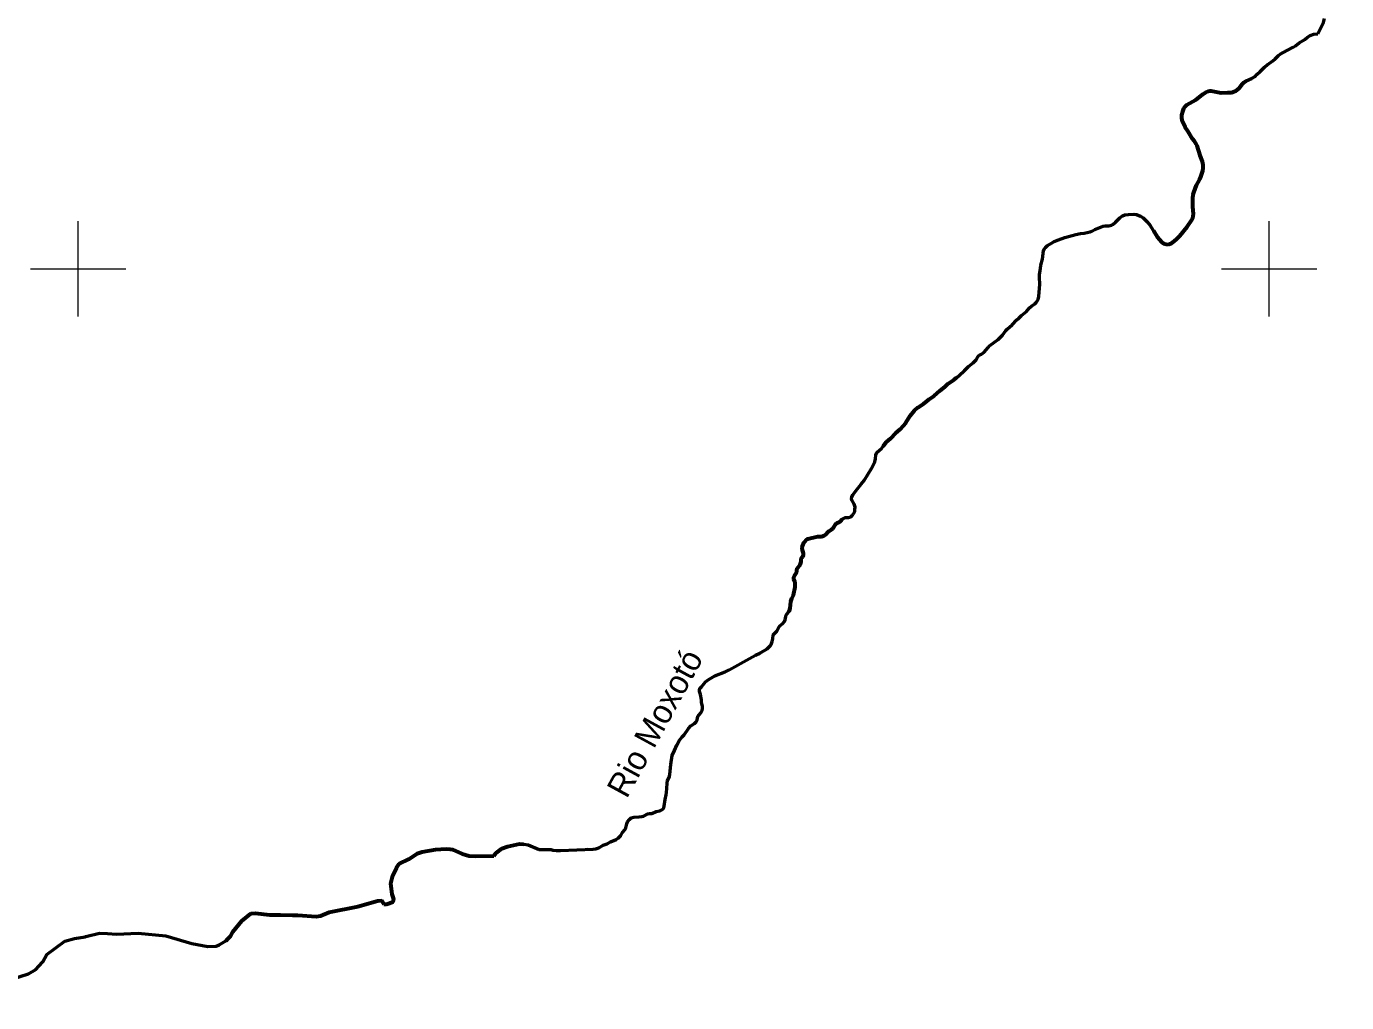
# Model space of a CAD drawing. Extents: x -1643653 to 4543381, y 1624270 to 13878484.
# Drawn here: x 598915 to 626625, y 8984602 to 9005087 of the extents above; entities that cross this region are included whole.
import ezdxf
from ezdxf.enums import TextEntityAlignment as Align

# ---------------------------------------------------------------- set-up
doc = ezdxf.new("R2010")
doc.units = 0
doc.header["$LTSCALE"] = 200
doc.linetypes.add('LONG_DASH_SHORT_DASH', pattern=[9.9, 6, -1.2, 1.5, -1.2])
for name, color, linetype, lineweight in [('1', 7, 'Continuous', 13), ('2', 7, 'Continuous', 13), ('24', 7, 'Continuous', 25), ('7', 7, 'LONG_DASH_SHORT_DASH', 60)]:
    doc.layers.add(name, color=color, linetype=linetype, lineweight=lineweight)
doc.layers.add('49', color=7, linetype='Continuous')

msp = doc.modelspace()

# ---------------------------------------------------------------- linework, layer by layer
at = {"layer": '1', "lineweight": 25}
msp.add_spline([(814781, 9009175.5), (814787.2, 9009173.4), (814796.9, 9009173.4), (814799.4, 9009172.4), (814805.1, 9009174.5), (814805.6, 9009176.5), (814811.7, 9009179.5), (814811.7, 9009179.5), (814801.5, 9009181), (814790.7, 9009181.5), (814784.1, 9009183.1), (814777.4, 9009185.1), (814778.4, 9009175.5)], degree=3, dxfattribs=at)
at = {"layer": '2'}
for p, q in [((600000, 8999000), (600000, 9001000)), ((625000, 8999000), (625000, 9001000)), ((599000, 9000000), (601000, 9000000)), ((624000, 9000000), (626000, 9000000))]:
    msp.add_line(p, q, dxfattribs=at)
at = {"layer": '24', "lineweight": 53}
for points in [[(626020.3, 9004931.6), (626138.4, 9005165.4), (626161, 9005249.2)], [(624968.7, 9004287.4), (625077.4, 9004367.4), (625125.3, 9004407.4), (625196.1, 9004475.4), (625232, 9004503.4), (625369.3, 9004583.4), (625507, 9004648.4), (625552.2, 9004680.4), (625627.3, 9004743.4), (625747.5, 9004813.4), (625804.8, 9004859.3), (625863.6, 9004898.3), (625936.5, 9004925.7), (626020.3, 9004931.6)], [(622356.1, 9001071.6), (622438.9, 9000988.6), (622501.2, 9000910.6), (622651.6, 9000673.6), (622694.8, 9000613.6), (622741.9, 9000562.6), (622781.6, 9000528.6), (622838, 9000513.6), (622887.5, 9000510.6), (622903.5, 9000513.6), (622951.5, 9000538.6), (623008.3, 9000580.6), (623061.1, 9000626.5), (623124.5, 9000694.5), (623279.2, 9000880.5), (623385, 9001031.5), (623398.2, 9001059.5), (623411.2, 9001147.5), (623406.1, 9001224.5), (623394.5, 9001300.5), (623396.9, 9001485.5), (623407.8, 9001557.5), (623420.7, 9001604.5), (623474.8, 9001753.5), (623546.5, 9001882.5), (623566.5, 9001928.5), (623606.4, 9002057.5), (623614.4, 9002114.5), (623615.2, 9002180.5), (623603.6, 9002252.5), (623548.9, 9002380.5), (623488.7, 9002579.5), (623465.3, 9002623.5), (623431.2, 9002675.5), (623387.3, 9002730.5), (623302, 9002882.5), (623235.1, 9002973.5), (623183.3, 9003094.5), (623167.7, 9003160.5), (623170, 9003229.5), (623186.6, 9003301.5), (623210, 9003362.5), (623241.9, 9003412.5), (623274.8, 9003442.5), (623462.1, 9003547.5), (623608.8, 9003667.5), (623666.2, 9003700.5), (623727.2, 9003726.5), (623755.6, 9003733.5), (623782.5, 9003731.5), (623993.5, 9003691.5), (624127.2, 9003701.5), (624209, 9003698.5), (624301.4, 9003736.4), (624324.7, 9003751.4), (624377.4, 9003798.4), (624433, 9003873.4), (624469.5, 9003912.4), (624514.8, 9003941.4), (624628.9, 9003992.4), (624709.5, 9004038.4), (624743.9, 9004077.4), (624810.6, 9004137.4), (624900.3, 9004230.4), (624968, 9004288.4)], [(620148.3, 8999353.7), (620168.6, 8999417.7), (620186.8, 8999678.7), (620178.1, 8999819.7), (620178.5, 8999880.7), (620194.3, 8999957.7), (620208.2, 9000078.7), (620242.8, 9000202.7), (620252.9, 9000329.7), (620263.2, 9000378.7), (620280.1, 9000412.7), (620305.3, 9000447.7), (620344.5, 9000485.7), (620432.6, 9000539.7), (620488.9, 9000569.7), (620581.6, 9000610.7), (620710.5, 9000657.7), (620939.4, 9000718.7), (621042.2, 9000740.6), (621118.4, 9000748.6), (621242.2, 9000776.6), (621275.5, 9000790.6), (621342.1, 9000826.6), (621518.2, 9000894.6), (621561.1, 9000901.6), (621637.2, 9000903.6), (621689.6, 9000916.6), (621716.6, 9000931.6), (621774.6, 9000977.6), (621867.2, 9001066.6), (621924.7, 9001110.6), (621967.5, 9001129.6), (622048.6, 9001140.6), (622160.3, 9001143.6), (622215.2, 9001136.6), (622300.1, 9001105.6), (622356.1, 9001071.6)], [(616275, 8994855), (616299.8, 8994916), (616306.6, 8994947), (616309.5, 8994997), (616289.9, 8995061), (616239.9, 8995143), (616235.6, 8995179), (616237.4, 8995206), (616262.8, 8995260), (616352.4, 8995378.9), (616439.6, 8995482.9), (616497.8, 8995558.9), (616654.6, 8995808.9), (616704.2, 8995904.9), (616721.4, 8995949.9), (616734.9, 8996009.9), (616742.4, 8996094.9), (616755.2, 8996130.9), (616770.5, 8996150.9), (616865.5, 8996231.9), (616968.5, 8996369.9), (617050.4, 8996439.9), (617160.7, 8996559.9), (617252.1, 8996633.9), (617320.9, 8996701.9), (617376, 8996767.9), (617466.2, 8996912.9), (617553.7, 8997026.9), (617627.5, 8997088.9), (617747.7, 8997167.8), (617821.7, 8997231.8), (617864.4, 8997264.8), (617970.3, 8997332.8), (618086, 8997441.8), (618201.6, 8997530.8), (618257.2, 8997582.8), (618380.8, 8997669.8), (618495.1, 8997763.8), (618608.2, 8997867.8), (618687.2, 8997947.8), (618784.2, 8998026.8), (618847.8, 8998091.8), (618880.8, 8998148.8), (618904.8, 8998177.8), (618927, 8998194.8), (618960.5, 8998211.8), (619017, 8998253.8), (619099.7, 8998350.8), (619132.8, 8998382.8), (619235.9, 8998457.8), (619310.3, 8998518.8), (619402.8, 8998610.8), (619472.9, 8998704.8), (619501.7, 8998736.7), (619608.1, 8998826.7), (619700.3, 8998928.7), (619746.9, 8998966.7), (619804.3, 8999021.7), (619907.6, 8999106.7), (619970.1, 8999177.7), (620010.3, 8999215.7), (620083.8, 8999267.7), (620109.1, 8999292.7), (620148.3, 8999353.7), (620148.3, 8999353.7)], [(615088.6, 8993660), (615092.1, 8993720), (615153, 8993790), (615174.6, 8993852), (615175.1, 8993904), (615179, 8993921), (615187.3, 8993934), (615211.5, 8993958), (615228.8, 8993992), (615227.7, 8994030), (615203.4, 8994096), (615199.3, 8994145), (615206.1, 8994178), (615239.1, 8994264), (615295.5, 8994325), (615320, 8994336), (615520.9, 8994382), (615601.5, 8994383), (615661.9, 8994403), (615699.6, 8994431), (615734.4, 8994474), (615755.4, 8994494), (615812.3, 8994527), (615840.8, 8994550), (615864.4, 8994578), (615900.1, 8994637), (615919.4, 8994659), (615934.8, 8994670), (615988.9, 8994692), (616008.8, 8994710), (616037.3, 8994745), (616076.4, 8994766), (616108.6, 8994778), (616169.1, 8994784), (616218.9, 8994795), (616250.2, 8994821), (616275, 8994855)], [(612374.7, 8989257.2), (612410.1, 8989349.2), (612422.8, 8989393.2), (612443.9, 8989595.2), (612472.1, 8989790.2), (612521.4, 8989889.2), (612567.7, 8990001.2), (612623.5, 8990108.2), (612679.4, 8990175.2), (612720.8, 8990217.2), (612815.3, 8990351.2), (612864.4, 8990407.2), (612937.9, 8990460.2), (612974.6, 8990496.2), (612997.1, 8990536.2), (613004.6, 8990605.2), (613071.9, 8990685.2), (613099.4, 8990741.2), (613104.8, 8990769.2), (613104.8, 8990813.2), (613086.3, 8990905.2), (613085.9, 8990954.2), (613066.1, 8991064.2), (613044.7, 8991133.2), (613043.4, 8991164.2), (613047.9, 8991196.2), (613081.7, 8991228.2), (613169.8, 8991332.2), (613227.7, 8991376.2), (613365.8, 8991458.1), (613579.6, 8991541.1), (613666.1, 8991582.1), (614090.8, 8991825.1), (614218.9, 8991891.1), (614310.9, 8991932.1), (614460.7, 8992023.1), (614532.5, 8992094.1), (614543.7, 8992113.1), (614569, 8992177.1), (614582, 8992234.1), (614589.2, 8992317.1), (614668.2, 8992394.1), (614704.5, 8992469.1), (614728, 8992505.1), (614788.8, 8992558.1), (614827.1, 8992602.1), (614841.2, 8992635.1), (614852.2, 8992705.1), (614861.2, 8992733.1), (614874, 8992755.1), (614920, 8992803.1), (614934.5, 8992832.1), (614943.5, 8992879.1), (614957.9, 8993016), (614981.1, 8993081), (615017.2, 8993154), (615053.5, 8993321), (615053.4, 8993409), (615046.2, 8993436), (615020.3, 8993489), (615020.7, 8993515), (615030.5, 8993541), (615082.9, 8993633), (615082.9, 8993633), (615088.6, 8993660)], [(610812.6, 8987820.3), (610868.6, 8987825.3), (610933, 8987849.3), (611023.7, 8987905.3), (611105.7, 8987931.3), (611174.3, 8987972.3), (611295.8, 8988024.3), (611334, 8988050.3), (611392.2, 8988106.3), (611428.2, 8988171.3), (611476.2, 8988225.3), (611496.6, 8988270.3), (611519.8, 8988356.3), (611535.1, 8988392.3), (611570.6, 8988443.3), (611611.3, 8988477.3), (611633.5, 8988486.3), (611663.2, 8988493.3), (611778.5, 8988500.3), (611831.3, 8988507.2), (611867.2, 8988517.2), (611960.5, 8988564.2), (611993.5, 8988570.2), (612040.4, 8988571.2), (612135.1, 8988609.2), (612211, 8988629.2), (612253, 8988646.2), (612280.4, 8988668.2), (612294.2, 8988690.2), (612304.8, 8988723.2), (612325, 8988861.2), (612344.1, 8988963.2), (612347.8, 8989019.2), (612358.9, 8989089.2), (612362.3, 8989210.2), (612374.7, 8989257.2)], [(606420.8, 8986668), (606473.8, 8986668.1), (606613.3, 8986714.2), (606626.1, 8986769), (606594.2, 8986880), (606564.5, 8987100.6), (606609.1, 8987266.3), (606681.2, 8987431.8), (606741, 8987512.8), (606939.6, 8987610), (607118.9, 8987727.3), (607224.8, 8987767.6), (607501, 8987816.5), (607722.2, 8987831.4), (607811.1, 8987818.7)], [(607811.1, 8987818.7), (607857.5, 8987812), (608058.1, 8987723), (608202.2, 8987682.7), (608346.4, 8987672.1), (608722.9, 8987680.8)], [(608722.9, 8987680.8), (608777.9, 8987747.6), (608897.1, 8987833.6), (609009.5, 8987880.2), (609264.4, 8987935.4), (609356.3, 8987924.6)], [(609356.3, 8987924.6), (609448.1, 8987913.7), (609678.6, 8987816.5)], [(609678.6, 8987816.5), (609919.3, 8987814.4), (609966, 8987801.4), (610032.6, 8987795.3), (610127.9, 8987794.3), (610812.6, 8987820.3)], [(604502.8, 8986438.7), (604614.5, 8986437.8), (604995.5, 8986406.1), (605088.3, 8986418.9), (605266.8, 8986501.7), (605873.8, 8986618.4), (606294.7, 8986737.4), (606369.1, 8986745.7), (606420.8, 8986668)], [(603138.8, 8985934.3), (603201.3, 8985995.2), (603246.4, 8986085.3), (603439.7, 8986316.8), (603622.3, 8986468.1), (603715.8, 8986478.2), (604022, 8986442.1), (604249.4, 8986440.5), (604502.8, 8986438.7)], [(599176.5, 8985365.4), (599258.9, 8985456.2), (599344, 8985609.2), (599718.7, 8985887.4)], [(599718.7, 8985887.4), (599721.5, 8985889.5), (599926.2, 8985947.2), (600149.2, 8985983.3), (600164.2, 8985987.1)], [(600164.2, 8985987.1), (600446.9, 8986057.4), (600614.3, 8986048.6)], [(600614.3, 8986048.6), (600805.6, 8986038.6), (601260, 8986057.6), (601842, 8986004.5), (602386.1, 8985845.2), (602725.9, 8985781.5), (602895.9, 8985787.9), (602963.8, 8985811.2), (603100.1, 8985896.5), (603138.8, 8985934.3)], [(598562.6, 8985004.4), (598611, 8985091.4), (598961, 8985203.4), (599114.5, 8985297), (599176.5, 8985365.4)]]:
    msp.add_lwpolyline(points, dxfattribs=at)
at = {"layer": '7', "lineweight": 35}
msp.add_line((610685.7, 8987847), (610687.2, 8987846.5), dxfattribs=at)
at = {"layer": '7'}
msp.add_line((603104.5, 8985900.8), (603138.8, 8985934.3), dxfattribs=at)
for points in [[(622572.2, 9000798.7), (622651.6, 9000673.6), (622694.8, 9000613.6), (622741.9, 9000562.6), (622781.6, 9000528.6), (622838, 9000513.6), (622887.5, 9000510.6), (622903.5, 9000513.6), (622951.5, 9000538.6), (623008.3, 9000580.6), (623061.1, 9000626.5), (623124.5, 9000694.5), (623279.2, 9000880.5), (623385, 9001031.5), (623398.2, 9001059.5), (623411.2, 9001147.5), (623406.1, 9001224.5), (623394.5, 9001300.5), (623396.9, 9001485.5), (623407.8, 9001557.5), (623420.7, 9001604.5), (623474.8, 9001753.5), (623546.5, 9001882.5), (623566.5, 9001928.5), (623606.4, 9002057.5), (623614.4, 9002114.5), (623615.2, 9002180.5), (623603.6, 9002252.5), (623548.9, 9002380.5), (623488.7, 9002579.5), (623465.3, 9002623.5), (623431.2, 9002675.5), (623387.3, 9002730.5), (623302, 9002882.5), (623235.1, 9002973.5), (623183.3, 9003094.5), (623167.7, 9003160.5), (623170, 9003229.5), (623186.6, 9003301.5), (623210, 9003362.5), (623241.9, 9003412.5), (623274.8, 9003442.5), (623462.1, 9003547.5), (623608.8, 9003667.5), (623666.2, 9003700.5), (623727.2, 9003726.5), (623755.6, 9003733.5), (623782.5, 9003731.5), (623993.5, 9003691.5), (624127.2, 9003701.5), (624209, 9003698.5), (624301.4, 9003736.4), (624324.7, 9003751.4), (624377.4, 9003798.4), (624433, 9003873.4), (624469.5, 9003912.4), (624514.8, 9003941.4)], [(616899, 8996276.8), (616968.5, 8996369.9), (617050.4, 8996439.9), (617160.7, 8996559.9), (617252.1, 8996633.9), (617320.9, 8996701.9), (617376, 8996767.9), (617466.2, 8996912.9), (617553.7, 8997026.9), (617627.5, 8997088.9), (617747.7, 8997167.8), (617821.7, 8997231.8), (617864.4, 8997264.8), (617970.3, 8997332.8), (618086, 8997441.8), (618201.6, 8997530.8), (618257.2, 8997582.8), (618380.8, 8997669.8), (618437.7, 8997716.6)], [(615088.6, 8993660), (615092.1, 8993720), (615153, 8993790), (615174.6, 8993852), (615175.1, 8993904), (615179, 8993921), (615187.3, 8993934), (615211.5, 8993958), (615228.8, 8993992), (615227.7, 8994030), (615203.4, 8994096), (615199.3, 8994145), (615206.1, 8994178), (615239.1, 8994264), (615295.5, 8994325), (615320, 8994336), (615520.9, 8994382), (615601.5, 8994383), (615661.9, 8994403), (615699.6, 8994431), (615734.4, 8994474), (615755.4, 8994494), (615812.3, 8994527), (615840.8, 8994550), (615864.4, 8994578), (615900.1, 8994637), (615919.4, 8994659), (615934.8, 8994670), (615988.9, 8994692), (616008.8, 8994710), (616037.3, 8994745)], [(614923.2, 8992809.3), (614934.5, 8992832.1), (614943.5, 8992879.1), (614957.9, 8993016), (614981.1, 8993081), (615017.2, 8993154), (615053.5, 8993321), (615053.4, 8993409), (615046.2, 8993436), (615020.3, 8993489), (615020.7, 8993515), (615030.5, 8993541), (615082.9, 8993633), (615082.9, 8993633), (615088.6, 8993660)], [(606420.8, 8986668), (606473.8, 8986668.1), (606613.3, 8986714.2), (606626.1, 8986769), (606594.2, 8986880), (606564.5, 8987100.6), (606609.1, 8987266.3), (606681.2, 8987431.8), (606741, 8987512.8), (606939.6, 8987610), (607118.9, 8987727.3), (607224.8, 8987767.6), (607501, 8987816.5), (607722.2, 8987831.4), (607811.1, 8987818.7)], [(607811.1, 8987818.7), (607857.5, 8987812), (608058.1, 8987723), (608202.2, 8987682.7), (608346.4, 8987672.1), (608722.9, 8987680.8)], [(608722.9, 8987680.8), (608777.9, 8987747.6), (608897.1, 8987833.6), (609009.5, 8987880.2), (609264.4, 8987935.4), (609347, 8987925.7)], [(604502.8, 8986438.7), (604614.5, 8986437.8), (604995.5, 8986406.1), (605088.3, 8986418.9), (605266.8, 8986501.7), (605873.8, 8986618.4), (606294.7, 8986737.4), (606369.1, 8986745.7), (606420.8, 8986668)], [(603138.8, 8985934.3), (603201.3, 8985995.2), (603246.4, 8986085.3), (603439.7, 8986316.8), (603622.3, 8986468.1), (603715.8, 8986478.2), (604022, 8986442.1), (604249.4, 8986440.5), (604502.8, 8986438.7)]]:
    msp.add_lwpolyline(points, dxfattribs=at)

# ---------------------------------------------------------------- texts
at = {"layer": '49'}
msp.add_text('Rio Moxotó', height=500, rotation=61.364, dxfattribs=at).set_placement((612325.1, 8990347.9), align=Align.CENTER)

doc.saveas('drawing.dxf')
